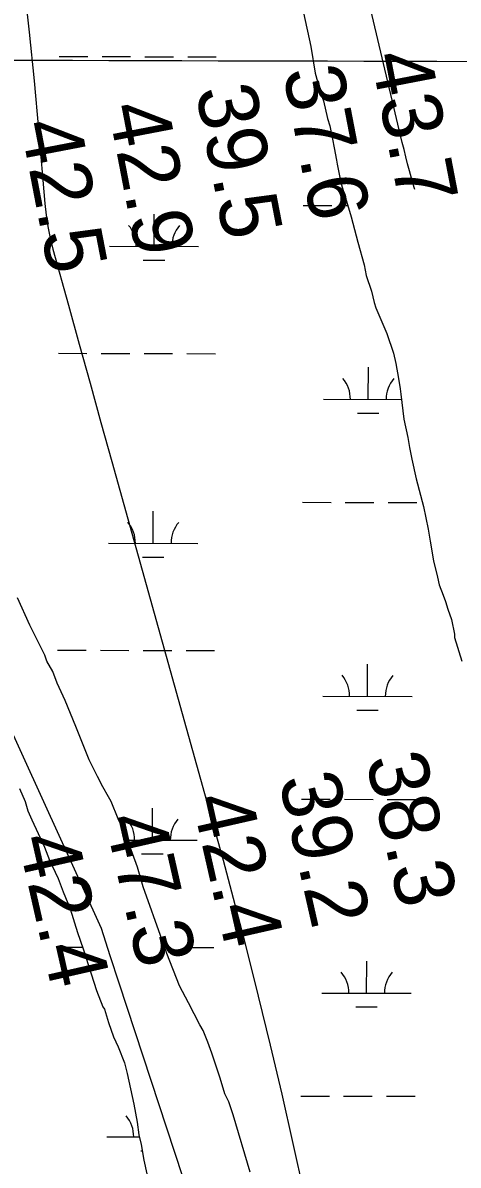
# Model space of a CAD drawing. Extents: x 3161665 to 3199565, y 885729 to 911164.
# Drawn here: x 3179188 to 3179675, y 895980 to 897260 of the extents above; entities that cross this region are included whole.
import ezdxf

# ---------------------------------------------------------------- set-up
doc = ezdxf.new("R2010")
doc.units = 0
for name, color, linetype in [('V-GRID-MAJR', 7, 'Continuous'), ('V-RIVR-RANG', 7, 'Continuous'), ('V-TOPO-MINR', 7, 'Continuous'), ('V-WETL-SWMP', 7, 'Continuous')]:
    doc.layers.add(name, color=color, linetype=linetype)

msp = doc.modelspace()

# ---------------------------------------------------------------- linework, layer by layer
at = {"layer": 'V-GRID-MAJR'}
msp.add_spline([(3165896.843, 897258.21), (3171121.2120000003, 897241.873), (3176345.5840000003, 897226.295), (3181569.957, 897211.478), (3186794.333, 897197.42), (3192018.711, 897184.122), (3197243.091, 897171.584), (3197243.092, 897171.584)], degree=3, dxfattribs=at)
at = {"layer": 'V-TOPO-MINR'}
for points in [[(3179626.8233314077, 897073.3977502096), (3179624.688014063, 897080.3016759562), (3179620.989120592, 897094.0243304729), (3179618.889656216, 897101.9595441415), (3179616.839417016, 897109.9072129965), (3179614.8630155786, 897117.8735646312), (3179612.9358393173, 897125.8523714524), (3179519.719435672, 897519.7825994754), (3179505.216365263, 897582.6179115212), (3179491.1769954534, 897645.5539795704), (3179477.833176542, 897708.6411816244), (3179464.953058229, 897771.8291396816), (3179445.646030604, 897869.2922087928), (3179442.8819208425, 897883.843826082), (3179440.270552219, 897898.4215690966), (3179437.8882953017, 897913.0385006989), (3179435.6587795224, 897927.6815580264), (3179364.3956989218, 898421.7518184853)], [(3179385.048032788, 895912.3644955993), (3179295.625001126, 896183.773940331), (3179285.694839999, 896214.451649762), (3179275.979247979, 896245.1959345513), (3178943.2248445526, 896975.3493151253), (3178942.87839248, 896978.3821940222), (3178942.708202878, 896981.4300488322), (3178942.412640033, 896992.4549297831), (3178942.4329190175, 896994.1037838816), (3178942.771017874, 896997.3706990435), (3178943.771943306, 897002.2266306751), (3178944.291539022, 897005.4947278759), (3178963.4115114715, 897808.7301279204)], [(3179188.892804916, 897303.7167019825), (3179195.0161790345, 897249.3584763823), (3179200.43393993, 897194.9253957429), (3179205.3812920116, 897140.4424117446), (3179212.373914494, 897057.4631128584), (3179213.831351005, 897044.4965322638), (3179215.7644873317, 897031.6149354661), (3179218.4111733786, 897018.8608143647), (3179221.533559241, 897006.1916770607), (3179238.786207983, 896943.7316644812), (3179250.913795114, 896899.9021447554), (3179263.0674317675, 896856.079862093), (3179275.2601427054, 896812.2684350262), (3179287.478903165, 896768.4642450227), (3179400.4731655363, 896364.0772155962), (3179412.1432930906, 896321.5899626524), (3179423.562976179, 896279.0366822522), (3179434.606992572, 896236.3843606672), (3179445.4005644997, 896193.6660116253), (3179451.4247741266, 896169.3731738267), (3179464.787858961, 896114.3998583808), (3179477.811377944, 896059.3478678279), (3179490.3255481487, 896004.1778646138), (3179502.500152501, 895948.9291862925)]]:
    msp.add_lwpolyline(points, dxfattribs=at)
at = {"layer": 'V-WETL-SWMP'}
for p, q in [((3179228.5338351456, 897222.331492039), (3179260.533708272, 897222.2430617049)), ((3179276.533644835, 897222.1988465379), (3179308.5335179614, 897222.110416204)), ((3179324.5334545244, 897222.0662010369), (3179356.533327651, 897221.9777707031)), ((3179372.533264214, 897221.9335555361), (3179404.5331373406, 897221.8451252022)), ((3179501.9815535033, 897055.401199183), (3179533.9814266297, 897055.3127688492)), ((3179549.9813631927, 897055.2685536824), (3179551.8448585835, 897055.2634039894)), ((3179334.7899138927, 897009.4330500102), (3179334.8893942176, 897045.4329118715)), ((3179284.790112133, 897009.5712224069), (3179384.789715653, 897009.2948776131)), ((3179322.747320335, 896994.035270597), (3179346.7472251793, 896993.9689478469)), ((3179227.614540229, 896889.6577685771), (3179259.614413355, 896889.569338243)), ((3179275.6143499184, 896889.5251230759), (3179307.6142230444, 896889.4366927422)), ((3179323.614159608, 896889.3924775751), (3179355.614032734, 896889.3040472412)), ((3179371.6139692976, 896889.2598320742), (3179403.6138424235, 896889.1714017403)), ((3179574.7889456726, 896837.9561736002), (3179574.888425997, 896873.9560354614)), ((3179524.7891439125, 896838.0943459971), (3179611.922308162, 896837.8535570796)), ((3179562.7463521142, 896822.5583941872), (3179586.7462569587, 896822.4920714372)), ((3179501.062258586, 896722.7274757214), (3179533.062131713, 896722.6390453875)), ((3179549.0620682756, 896722.5948302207), (3179581.061941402, 896722.5063998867)), ((3179597.061877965, 896722.4621847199), (3179629.0617510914, 896722.3737543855)), ((3179333.870618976, 896676.7593265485), (3179333.970099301, 896712.7591884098)), ((3179283.8708172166, 896676.8974989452), (3179383.8704207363, 896676.6211541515)), ((3179321.828025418, 896661.3615471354), (3179345.827930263, 896661.2952243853)), ((3179226.6952453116, 896556.9840451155), (3179258.6951184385, 896556.8956147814)), ((3179274.6950550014, 896556.8513996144), (3179306.694928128, 896556.7629692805)), ((3179322.694864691, 896556.7187541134), (3179354.694737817, 896556.6303237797)), ((3179370.6946743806, 896556.5861086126), (3179402.694547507, 896556.4976782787)), ((3179573.8696507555, 896505.2824501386), (3179573.9691310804, 896541.2823119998)), ((3179523.8698489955, 896505.4206225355), (3179623.8694525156, 896505.1442777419)), ((3179561.827057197, 896489.8846707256), (3179585.826962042, 896489.8183479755)), ((3179332.9513240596, 896344.0856030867), (3179333.050804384, 896380.085464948)), ((3179500.1429636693, 896390.0537522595), (3179532.1428367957, 896389.9653219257)), ((3179548.142773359, 896389.9211067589), (3179580.1426464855, 896389.8326764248)), ((3179596.1425830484, 896389.7884612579), (3179628.142456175, 896389.7000309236)), ((3179305.046887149, 896344.1627158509), (3179382.9511258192, 896343.9474306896)), ((3179320.9087305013, 896328.6878236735), (3179344.9086353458, 896328.6215009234)), ((3179225.7759503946, 896224.3103216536), (3179254.587464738, 896224.230702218)), ((3179346.846784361, 896223.9757473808), (3179353.7754429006, 896223.9566003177)), ((3179369.7753794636, 896223.9123851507), (3179401.7752525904, 896223.8239548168)), ((3179572.950355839, 896172.6087266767), (3179573.0498361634, 896208.6085885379)), ((3179522.9505540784, 896172.7468990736), (3179622.950157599, 896172.4705542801)), ((3179560.9077622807, 896157.2109472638), (3179584.9076671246, 896157.1446245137)), ((3179499.2236687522, 896057.3800287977), (3179531.2235418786, 896057.2915984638)), ((3179547.223478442, 896057.247383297), (3179579.2233515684, 896057.1589529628)), ((3179595.223288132, 896057.1147377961), (3179627.223161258, 896057.0263074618)), ((3179282.0322273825, 896011.5500520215), (3179318.3847072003, 896011.449593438)), ((3179319.9894355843, 895996.0141002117), (3179321.5530768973, 895996.0097791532))]:
    msp.add_line(p, q, dxfattribs=at)
for points in [[(3179502.205000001, 897271.1059999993), (3179510.349000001, 897233.4559999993), (3179515.311000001, 897203.6069999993), (3179519.726000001, 897187.3719999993), (3179520.998000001, 897184.1219999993), (3179521.622000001, 897180.8769999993), (3179524.799000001, 897172.4279999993), (3179529.190000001, 897152.9529999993), (3179531.719000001, 897144.5089999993), (3179534.848000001, 897129.5799999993), (3179536.720000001, 897119.8439999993), (3179539.210000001, 897106.2159999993), (3179539.824000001, 897101.6749999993), (3179543.572000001, 897082.8519999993), (3179545.463000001, 897075.7089999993), (3179549.264000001, 897064.0149999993), (3179555.585000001, 897042.5809999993), (3179563.148000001, 897014.0089999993), (3179570.088000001, 896988.6819999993), (3179572.593000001, 896976.9969999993), (3179578.295000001, 896959.4559999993), (3179581.438000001, 896946.4709999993), (3179583.339000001, 896940.6239999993), (3179595.438000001, 896912.0179999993), (3179603.050000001, 896889.9259999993), (3179605.555000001, 896878.2419999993), (3179608.670000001, 896861.3689999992), (3179610.527000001, 896849.6889999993), (3179611.131000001, 896843.8519999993), (3179614.811000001, 896815.9569999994), (3179619.193000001, 896795.1849999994), (3179621.054000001, 896784.1539999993), (3179623.550000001, 896771.1729999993), (3179628.569000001, 896749.1009999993), (3179636.762000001, 896717.9319999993), (3179641.757000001, 896692.6189999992), (3179644.248000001, 896678.9909999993), (3179647.971000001, 896656.9279999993), (3179652.372000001, 896638.7489999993), (3179654.253000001, 896630.3089999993), (3179658.702000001, 896618.6109999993), (3179661.241000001, 896611.4629999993), (3179663.770000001, 896603.0189999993), (3179668.220000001, 896591.3199999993), (3179671.339000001, 896575.0939999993), (3179671.310000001, 896571.2059999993), (3179679.5360000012, 896544.5729999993)], [(3179442.595000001, 895972.1399999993), (3179423.633000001, 896036.4419999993), (3179418.555000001, 896050.7379999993), (3179414.087000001, 896059.8449999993), (3179409.033000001, 896077.3809999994), (3179399.520000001, 896105.3199999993), (3179395.076000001, 896117.6669999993), (3179389.989000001, 896130.6659999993), (3179386.149000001, 896137.1759999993), (3179373.372000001, 896161.8989999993), (3179363.143000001, 896180.7689999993), (3179349.158000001, 896217.1669999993), (3179344.085000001, 896232.1109999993), (3179322.496000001, 896291.8959999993), (3179316.181000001, 896313.9779999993), (3179303.476000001, 896348.4209999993), (3179294.549000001, 896367.9309999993), (3179286.918000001, 896387.4299999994), (3179283.716000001, 896392.6389999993), (3179277.318000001, 896403.7039999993), (3179271.573000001, 896415.4129999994), (3179261.992000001, 896434.2789999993), (3179247.363000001, 896471.3289999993), (3179235.268000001, 896500.5829999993), (3179226.341000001, 896520.0929999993), (3179221.254000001, 896533.0919999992), (3179214.860000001, 896544.8059999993), (3179212.316000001, 896551.3049999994), (3179195.719000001, 896585.1299999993), (3179181.690000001, 896615.6949999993)], [(3179183.980000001, 896401.8089999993), (3179190.354000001, 896387.5039999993), (3179193.516000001, 896377.1109999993), (3179197.975000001, 896366.7079999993), (3179212.005000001, 896336.1429999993), (3179217.730000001, 896321.8429999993), (3179227.296000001, 896301.0319999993), (3179233.017000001, 896286.0839999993), (3179240.653000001, 896267.2319999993), (3179248.879000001, 896240.5989999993), (3179255.224000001, 896222.4049999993), (3179270.429000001, 896175.6299999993), (3179277.422000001, 896157.4309999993), (3179279.347000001, 896154.8239999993), (3179283.771000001, 896139.8849999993), (3179289.483000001, 896123.6399999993), (3179294.585000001, 896112.5849999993), (3179301.578000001, 896094.3859999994), (3179304.731000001, 896082.6969999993), (3179312.251000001, 896048.2919999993), (3179315.989000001, 896028.1739999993), (3179317.827000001, 896013.9019999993), (3179320.336000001, 896002.8659999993), (3179323.446000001, 895985.3439999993), (3179330.971000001, 895951.5879999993)]]:
    msp.add_lwpolyline(points, dxfattribs=at)
for centre, radius, start, end in [((3179279.548508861, 897010.0605123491), 35.24628790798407, 359.069845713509, 40.613504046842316), ((3179390.033943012, 897009.7551903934), 35.24628790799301, 139.06984290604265, 180.61350123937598), ((3179519.547540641, 896838.5836359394), 35.24628790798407, 359.069845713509, 40.613504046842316), ((3179630.0329747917, 896838.2783139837), 35.24628790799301, 139.06984290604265, 180.61350123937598), ((3179278.6292139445, 896677.3867888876), 35.24628790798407, 359.069845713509, 40.613504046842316), ((3179389.114648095, 896677.0814669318), 35.24628790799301, 139.06984290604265, 180.61350123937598), ((3179518.6282457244, 896505.9099124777), 35.24628790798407, 359.069845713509, 40.613504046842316), ((3179629.1136798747, 896505.6045905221), 35.24628790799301, 139.06984290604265, 180.61350123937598), ((3179277.7099190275, 896344.7130654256), 35.24628790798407, 359.069845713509, 40.613504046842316), ((3179388.1953531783, 896344.4077434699), 35.24628790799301, 139.06984290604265, 180.61350123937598), ((3179517.7089508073, 896173.2361890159), 35.24628790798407, 359.069845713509, 40.613504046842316), ((3179628.194384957, 896172.9308670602), 35.24628790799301, 139.06984290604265, 180.61350123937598), ((3179276.7906241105, 896012.0393419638), 35.24628790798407, 359.069845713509, 40.613504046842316)]:
    msp.add_arc(centre, radius, start, end, dxfattribs=at)

# ---------------------------------------------------------------- texts
at = {"layer": 'V-RIVR-RANG'}
for s, height, rotation, p in [('43.7', 66.99999999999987, 280.8983257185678, (3179577.4928261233, 897223.2451921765)), ('37.6', 66.99999999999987, 280.8983257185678, (3179478.9947225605, 897205.907346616)), ('39.5', 66.99999999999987, 280.8983257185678, (3179381.1948261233, 897184.9421921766)), ('42.9', 66.99999999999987, 280.8983257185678, (3179282.995954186, 897166.0502142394)), ('42.5', 66.99999999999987, 280.8983257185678, (3179184.8968261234, 897146.6401921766)), ('38.3', 67, 282.79832571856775, (3179571.717681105, 896434.9708445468)), ('39.2', 67, 282.79832571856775, (3179474.2566811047, 896412.5808445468)), ('42.4', 67, 282.79832571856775, (3179376.7956811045, 896390.1908445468)), ('47.3', 67, 282.79832571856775, (3179279.3336811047, 896367.8008445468)), ('42.4', 67, 282.79832571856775, (3179181.8726811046, 896345.4108445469))]:
    msp.add_text(s, height=height, rotation=rotation, dxfattribs=at).set_placement(p)

doc.saveas('drawing.dxf')
